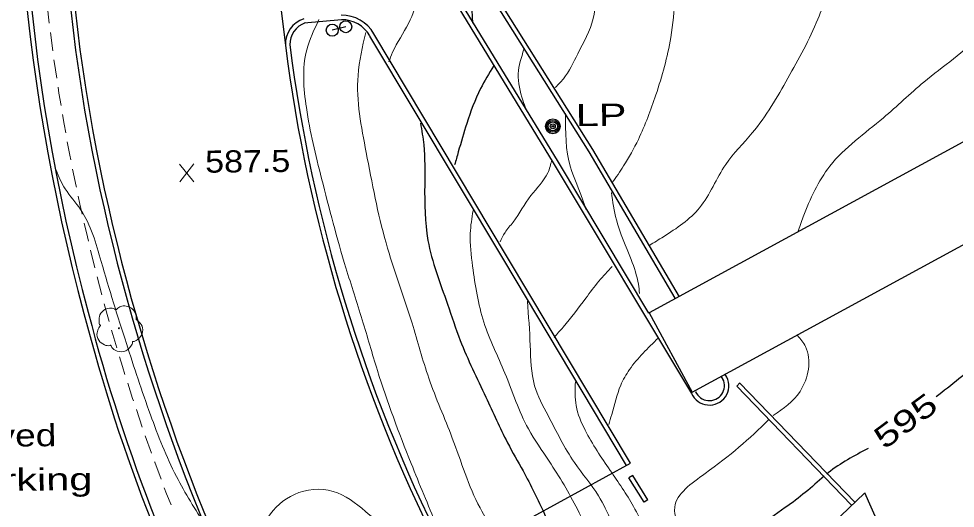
# Model space of a CAD drawing. Extents: x 2361708 to 2370558, y 6977955 to 6991887.
# Drawn here: x 2369439 to 2369642.1, y 6991258.2 to 6991364.4 of the extents above; entities that cross this region are included whole.
import ezdxf
from ezdxf.enums import TextEntityAlignment as Align

# ---------------------------------------------------------------- set-up
doc = ezdxf.new("R2010")
doc.units = 0
doc.header["$LTSCALE"] = 1.9
for name, color, linetype, lineweight in [('11', 7, 'Continuous', 25), ('13', 7, 'Continuous', 13), ('2', 7, 'Continuous', 25), ('20', 7, 'Continuous', 25), ('21', 7, 'Continuous', 25), ('29', 7, 'Continuous', 13), ('31', 7, 'Continuous', 13), ('35', 7, 'Continuous', 13)]:
    doc.layers.add(name, color=color, linetype=linetype, lineweight=lineweight)

msp = doc.modelspace()

# ---------------------------------------------------------------- linework, layer by layer
at = {"layer": '11'}
msp.add_lwpolyline([(2369732.214, 6991385.783), (2369575.717, 6991300.58), (2369585.051, 6991283.438), (2369741.558, 6991368.601)], close=True, dxfattribs=at)
msp.add_lwpolyline([(2369622.371, 6991261.532), (2369600.312, 6991240.341), (2369607.79, 6991223.771), (2369629.932, 6991244.733), (2369622.5, 6991261.613)], dxfattribs=at)
at = {"layer": '13'}
for p, q in [((2369445.653, 6991363.375), (2369445.205, 6991367.35)), ((2369446.4, 6991357.421), (2369445.892, 6991361.387)), ((2369455.539, 6991310.326), (2369454.602, 6991314.217)), ((2369457.024, 6991304.52), (2369456.027, 6991308.39)), ((2369458.619, 6991298.735), (2369457.533, 6991302.585)), ((2369465.797, 6991275.852), (2369464.521, 6991279.64)), ((2369467.801, 6991270.191), (2369466.455, 6991273.958))]:
    msp.add_line(p, q, dxfattribs=at)
for points in [[(2369447.256, 6991351.479), (2369446.702, 6991355.054), (2369446.649, 6991355.434)], [(2369448.193, 6991345.558), (2369447.747, 6991348.254), (2369447.555, 6991349.502)], [(2369449.199, 6991339.637), (2369448.861, 6991341.504), (2369448.522, 6991343.581)], [(2369450.306, 6991333.738), (2369450.086, 6991334.786), (2369449.558, 6991337.67)], [(2369451.522, 6991327.869), (2369451.48, 6991328.058), (2369450.704, 6991331.781)], [(2369452.777, 6991322.001), (2369452.277, 6991324.196), (2369451.92, 6991325.913)], [(2369454.133, 6991316.163), (2369453.904, 6991317.101), (2369453.226, 6991320.055)], [(2369460.294, 6991292.981), (2369459.406, 6991295.912), (2369459.157, 6991296.81)], [(2369462.059, 6991287.247), (2369461.523, 6991288.942), (2369460.872, 6991291.066)], [(2369463.883, 6991281.534), (2369463.719, 6991282.013), (2369462.667, 6991285.343)], [(2369469.875, 6991264.56), (2369468.5, 6991268.218), (2369468.469, 6991268.307)], [(2369472.038, 6991258.961), (2369471.066, 6991261.382), (2369470.573, 6991262.687)]]:
    msp.add_lwpolyline(points, dxfattribs=at)
at = {"layer": '2'}
for p, q in [((2369493.158, 6991388.368), (2369496.841, 6991358.642)), ((2369509.039, 6991364.148), (2369500.916, 6991363.401)), ((2369591.745, 6991286.172), (2369591.318, 6991286.897)), ((2369592.571, 6991286.659), (2369592.143, 6991287.375)), ((2369585.597, 6991283.823), (2369585.729, 6991283.604)), ((2369594.699, 6991284.719), (2369595.383, 6991285.396)), ((2369619.525, 6991258.985), (2369594.699, 6991284.719)), ((2369620.3, 6991259.562), (2369595.393, 6991285.386)), ((2369535.742, 6991248.387), (2369571.647, 6991268.039)), ((2369572.153, 6991265.344), (2369571.337, 6991264.836)), ((2369574.628, 6991259.527), (2369571.337, 6991264.836)), ((2369575.443, 6991260.035), (2369572.153, 6991265.344)), ((2369575.443, 6991260.035), (2369574.628, 6991259.527))]:
    msp.add_line(p, q, dxfattribs=at)
for points in [[(2369581.357, 6991303.804), (2369562.704, 6991335.487), (2369523.103, 6991398.494)], [(2369582.314, 6991304.072), (2369563.519, 6991335.985), (2369523.918, 6991399.001)], [(2369529.001, 6991375.628), (2369554.927, 6991333.104), (2369584.904, 6991283.106)], [(2369529.816, 6991376.126), (2369555.752, 6991333.601), (2369575.598, 6991300.498)], [(2369571.647, 6991268.039), (2369544.991, 6991312.588), (2369515.998, 6991361.104)], [(2369570.822, 6991267.541), (2369544.166, 6991312.1), (2369515.173, 6991360.616)]]:
    msp.add_lwpolyline(points, dxfattribs=at)
for centre, radius, start, end in [((2369827.915, 6991407.758), 379.901, 171.06614, 192.2312), ((2369827.915, 6991407.758), 378.941, 171.06614, 192.2312), ((2369862.608, 6991411.052), 424.115, 173.10051, 195.11334), ((2369862.608, 6991411.052), 423.155, 173.10051, 195.11334), ((2369509.135, 6991357.226), 7.883, 29.47018, 91.3476), ((2369502.687, 6991358.815), 5.849, 108.54983, 181.69942), ((2369502.687, 6991358.815), 4.889, 108.54983, 181.69942), ((2369509.135, 6991357.226), 6.923, 29.47018, 91.3476), ((2369832.662, 6991401.317), 338.522, 187.24227, 206.63381), ((2369832.662, 6991401.317), 337.562, 187.24227, 206.63381), ((2369872.906, 6991417.223), 425.876, 192.19326, 209.77936), ((2369872.906, 6991417.223), 424.916, 192.19326, 209.77936), ((2369820.831, 6991395.025), 379.632, 194.42212, 208.80254), ((2369820.831, 6991395.025), 378.671, 194.42212, 208.80254), ((2369588.762, 6991284.83), 4.225, 204.07355, 25.65811), ((2369588.762, 6991284.83), 3.265, 204.07355, 25.65811)]:
    msp.add_arc(centre, radius, start, end, dxfattribs=at)
at = {"layer": '20'}
for radius in [1.6, 1.3, 1, 0.539, 0.192]:
    msp.add_circle((2369554.821, 6991341.033), radius, dxfattribs=at)
at = {"layer": '21'}
msp.add_line((2369509.923, 6991362.636), (2369507.011, 6991361.889), dxfattribs=at)
for centre in [(2369507.003, 6991361.876), (2369509.916, 6991362.624)]:
    msp.add_circle(centre, 1.3, dxfattribs=at)
at = {"layer": '29'}
msp.add_circle((2369460.743, 6991297.255), 0.1, dxfattribs=at)
for points in [[(2369456.778, 6991297.827), (2369456.797, 6991297.838), (2369456.717, 6991297.907), (2369456.481, 6991298.534), (2369456.519, 6991299.815), (2369457.406, 6991301.113), (2369458.712, 6991301.596), (2369459.834, 6991301.406), (2369460.065, 6991301.278), (2369460.135, 6991301.279), (2369460.185, 6991301.32), (2369460.532, 6991301.613), (2369461.398, 6991302.061), (2369462.608, 6991301.993), (2369463.724, 6991301.403), (2369464.458, 6991299.981), (2369464.466, 6991299.121)], [(2369464.456, 6991299.141), (2369465.596, 6991298.081), (2369465.881, 6991296.494), (2369465.173, 6991295.167), (2369464.519, 6991294.621), (2369463.851, 6991294.404), (2369463.701, 6991294.393), (2369463.682, 6991294.283), (2369463.36, 6991293.38), (2369461.821, 6991292.215), (2369459.929, 6991292.497), (2369459.029, 6991293.438), (2369458.958, 6991293.568), (2369458.838, 6991293.547), (2369457.627, 6991293.665), (2369456.358, 6991294.663), (2369456.012, 6991296.3), (2369456.382, 6991297.323), (2369456.708, 6991297.767), (2369456.778, 6991297.818)]]:
    msp.add_spline(points, degree=3, dxfattribs=at)
at = {"layer": '31'}
for p, q in [((2369477.012, 6991329.011), (2369473.895, 6991332.862)), ((2369473.932, 6991328.982), (2369476.975, 6991332.891))]:
    msp.add_line(p, q, dxfattribs=at)
at = {"layer": '31', "lineweight": 25}
for points in [[(2369537.557, 6991376.02), (2369537.412, 6991371.378), (2369537.242, 6991367.097), (2369537.428, 6991363.398)], [(2369541.966, 6991354.111), (2369539.142, 6991349.204), (2369536.155, 6991341.655), (2369534.333, 6991335.498), (2369533.539, 6991332.69)], [(2369526.133, 6991341.73), (2369526.828, 6991336.996), (2369527.04, 6991328.358), (2369527.745, 6991316.314), (2369531.987, 6991302.483), (2369534.742, 6991294.639), (2369540.309, 6991282.342), (2369544.994, 6991272.436), (2369548.362, 6991266.327), (2369553.042, 6991256.922), (2369557.199, 6991246.731), (2369560.347, 6991237.54), (2369564.165, 6991230.386), (2369565.963, 6991226.413)], [(2369690.482, 6991340.604), (2369691.078, 6991336.769), (2369694.343, 6991326.79), (2369695.273, 6991316.338), (2369682.498, 6991306.326), (2369663.528, 6991297.765), (2369652.649, 6991293.481), (2369642.867, 6991286.268), (2369637.904, 6991282.381)], [(2369623.159, 6991271.2), (2369614.549, 6991265.917), (2369614.221, 6991265.654)], [(2369613.646, 6991265.189), (2369605.231, 6991258.368), (2369599.358, 6991253.383), (2369597.514, 6991249.514), (2369596.318, 6991247.073)]]:
    msp.add_spline(points, degree=3, dxfattribs=at)
at = {"layer": '35'}
for points in [[(2369609.31, 6991486.439), (2369607.027, 6991479.317), (2369598.121, 6991464.221), (2369583.279, 6991441.219), (2369570.462, 6991417.755), (2369566.477, 6991400.347), (2369565.098, 6991385.582), (2369564.083, 6991372.372), (2369563.589, 6991364.397), (2369560.212, 6991356.765), (2369557.113, 6991351.335), (2369555.361, 6991349.478)], [(2369639.596, 6991484.857), (2369633.608, 6991479.38), (2369624.609, 6991469.823), (2369614.216, 6991453.243), (2369605.891, 6991443.264), (2369599.064, 6991432.388), (2369590.629, 6991418.077), (2369587.922, 6991405.181), (2369585.219, 6991391.765), (2369582.272, 6991377.856), (2369580.399, 6991360.267), (2369577.167, 6991347.856), (2369573.369, 6991338.199), (2369570.174, 6991332.448), (2369567.698, 6991328.825)], [(2369661.975, 6991485.109), (2369657.401, 6991479.166), (2369649.17, 6991470.797), (2369642.69, 6991461.405), (2369638.225, 6991450.362), (2369625.011, 6991432.835), (2369617.763, 6991421.016), (2369616.884, 6991411.387), (2369616.987, 6991402.697), (2369617.301, 6991389.68), (2369615.584, 6991374.672), (2369612.293, 6991364.281), (2369605.784, 6991351.458), (2369598.077, 6991339.604), (2369592.312, 6991332.769), (2369586.631, 6991323.394), (2369578.81, 6991317.11), (2369575.768, 6991315.221)], [(2369681.829, 6991484.758), (2369679.644, 6991477.958), (2369676.519, 6991469.057), (2369671.47, 6991460.419), (2369666.077, 6991450.257), (2369659.649, 6991437.455), (2369654.157, 6991426.042), (2369651.799, 6991416.319), (2369650.245, 6991407.284), (2369648.447, 6991395.526), (2369649.317, 6991386.064), (2369652.494, 6991374.884), (2369652.02, 6991367.919), (2369647.764, 6991361.158), (2369635.274, 6991350.629), (2369626.487, 6991342.875), (2369614.896, 6991332.424), (2369609.131, 6991321.429), (2369607.942, 6991318.087)], [(2369528.746, 6991376.126), (2369526.058, 6991369.6), (2369523.518, 6991363.346), (2369520.097, 6991357.083), (2369519.257, 6991354.995)], [(2369504.099, 6991364.161), (2369501.461, 6991357.585), (2369501.39, 6991345.084), (2369504.687, 6991329.725), (2369509.971, 6991310.334), (2369513.519, 6991299.068), (2369516.793, 6991288.108), (2369524.095, 6991267.957), (2369529.644, 6991254.489), (2369531.762, 6991249.409)], [(2369514.266, 6991361.397), (2369512.584, 6991352.061), (2369514.363, 6991335.397), (2369518.67, 6991315.747), (2369524.316, 6991298.38), (2369527.939, 6991286.424), (2369533.023, 6991273.452), (2369539.048, 6991258.298), (2369545.468, 6991247.889), (2369550.17, 6991237.123), (2369551.587, 6991226.926), (2369554.953, 6991214.747), (2369559.86, 6991203.544), (2369563.705, 6991194.62)], [(2369548.562, 6991357.734), (2369547.342, 6991352.442), (2369548.337, 6991346.671), (2369548.975, 6991344.777)], [(2369557.545, 6991343.798), (2369558.646, 6991332.179), (2369560.892, 6991326.25), (2369562.013, 6991322.98)], [(2369554.591, 6991333.73), (2369553.727, 6991330.942), (2369550.074, 6991326.027), (2369546.199, 6991320.26), (2369544.46, 6991318.033), (2369543.379, 6991316.012)], [(2369479.542, 6991254.482), (2369473.2, 6991265.142), (2369467.592, 6991278.499), (2369462.355, 6991293.99), (2369456.905, 6991311.729), (2369452.428, 6991322.997), (2369449.115, 6991327.456), (2369447.106, 6991331.527)], [(2369567.538, 6991326.693), (2369568.595, 6991320.753), (2369571.797, 6991312.183), (2369573.368, 6991306.787), (2369573.617, 6991304.76)], [(2369537.524, 6991322.787), (2369536.932, 6991317.811), (2369537.439, 6991310.685), (2369539.875, 6991298.558), (2369544.45, 6991287.511), (2369549.515, 6991275.429), (2369554.022, 6991268.412), (2369560.152, 6991258.009), (2369566.105, 6991246.125), (2369575.075, 6991234.59), (2369584.885, 6991224.113), (2369590.009, 6991214.301), (2369585.956, 6991202.002), (2369589.779, 6991192.228), (2369594.447, 6991179.902), (2369600.583, 6991170.88), (2369608.272, 6991165.753), (2369614.606, 6991162.263), (2369619.864, 6991160.393)], [(2369567.721, 6991310.674), (2369564.782, 6991307.456), (2369561.976, 6991303.769), (2369557.065, 6991297.522), (2369555.097, 6991295.253)], [(2369343.337, 6991307.828), (2369343.936, 6991295.313), (2369346.744, 6991282.989), (2369348.563, 6991265.166), (2369351.268, 6991249.991), (2369355.956, 6991229.204), (2369357.579, 6991220.529), (2369359.181, 6991213.974), (2369365.211, 6991211.952), (2369375, 6991211.035), (2369389.963, 6991211.877), (2369401.589, 6991211.278), (2369414.869, 6991213.404), (2369428.679, 6991215.596), (2369439.185, 6991217.136), (2369446.685, 6991218.158), (2369455.55, 6991214.611), (2369462.605, 6991207.718), (2369466.782, 6991202.908), (2369467.549, 6991202.125)], [(2369549.312, 6991303.118), (2369549.923, 6991293.533), (2369550.876, 6991284.812), (2369553.778, 6991278.37), (2369559.525, 6991268.124), (2369564.724, 6991260.903), (2369570.13, 6991249.854), (2369578.025, 6991238.869), (2369585.231, 6991231.927), (2369593.476, 6991225.145), (2369598.344, 6991215.881), (2369598.925, 6991206.426), (2369603.423, 6991196.108), (2369609.005, 6991189.681), (2369616.556, 6991181.183), (2369621.769, 6991174.572), (2369629.045, 6991169.781), (2369636.007, 6991168.527), (2369640.099, 6991168.386)], [(2369577.669, 6991295.118), (2369571.454, 6991288.298), (2369569.546, 6991284.9), (2369567.587, 6991278.551), (2369566.937, 6991276.365)], [(2369607.865, 6991295.725), (2369609.609, 6991293.272), (2369608.421, 6991283.58), (2369602.63, 6991278.364)], [(2369559.709, 6991285.616), (2369559.888, 6991280.498), (2369561.828, 6991275.166), (2369567.262, 6991266.448), (2369572.307, 6991258.615), (2369577.114, 6991249.451), (2369582.833, 6991241.195), (2369589.893, 6991233.871), (2369597.976, 6991226.208), (2369603.937, 6991216.684), (2369608.574, 6991210.778), (2369618.236, 6991205.34), (2369632.672, 6991202.677), (2369641.767, 6991199.053), (2369645.827, 6991192.802), (2369648.611, 6991186.078), (2369652.292, 6991181.833), (2369657.359, 6991180.001), (2369661.441, 6991180.79), (2369663.763, 6991181.732)], [(2369601.678, 6991277.505), (2369601.668, 6991277.495), (2369587.82, 6991265.743), (2369581.248, 6991258.49), (2369583.027, 6991252.337), (2369586.012, 6991246.485), (2369591.753, 6991238.089), (2369596.849, 6991231.187), (2369602.016, 6991225.246), (2369608.481, 6991217.348), (2369617.012, 6991209.998), (2369626.065, 6991209.664), (2369637.925, 6991207.607), (2369648.552, 6991202.698), (2369656.051, 6991198.739), (2369659.262, 6991197.62), (2369659.887, 6991198.056)], [(2369542.817, 6991226.903), (2369534.05, 6991235.98), (2369523.429, 6991248.699), (2369514.194, 6991257.552), (2369507.162, 6991261.895), (2369498.778, 6991261.245), (2369493.016, 6991256.22), (2369489.729, 6991247.469), (2369490.2, 6991238.893), (2369494.134, 6991227.979), (2369498.437, 6991218.27), (2369504.039, 6991206.503)]]:
    msp.add_spline(points, degree=3, dxfattribs=at)

# ---------------------------------------------------------------- texts
at = {"layer": '2'}
for s, width, p in [('Paved', 1.25, (2369424.447, 6991271.488)), ('Parking', 1.4, (2369424.538, 6991261.889))]:
    msp.add_text(s, height=4.8, rotation=0.545, dxfattribs=dict(at, width=width)).set_placement(p)
at = {"layer": '20', "width": 1.4}
msp.add_text('  LP', height=4.8, rotation=0.545, dxfattribs=at).set_placement((2369554.821, 6991341.033))
at = {"layer": '31', "width": 1.15}
msp.add_text('587.5', height=4.8, rotation=0.545, dxfattribs=at).set_placement((2369479.453, 6991330.975))
at = {"layer": '31', "width": 1.4}
msp.add_text(' 595 ', height=4.8, rotation=36.455, dxfattribs=at).set_placement((2369632.711, 6991275.281), align=Align.CENTER)

doc.saveas('drawing.dxf')
